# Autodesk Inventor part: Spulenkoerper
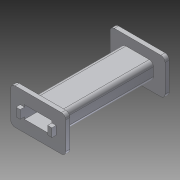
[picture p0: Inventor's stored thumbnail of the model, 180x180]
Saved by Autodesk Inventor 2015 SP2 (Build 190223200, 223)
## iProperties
Created: 2015-10
Part Number: Spulenkoerper
Material: PC/ABS-Kunststoff
Document SubType Name: Modeling
Designer: rYan
Mass: 0.345661 g
Surface Area: 21.13 cm^2
Volume: 0.9675 cm^3
Density: 0.357273 g/cm^3
Appearance: Glatt - weiß
Author: rYan
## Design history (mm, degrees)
sketch "Skizze1"
  geometry: L1 (-10.5, 0)-(10.5, 0) reference; L2 (0, -0.8)-(0, 4.8) reference; L3 (6.5, 3)-(-6.5, 3); L4 (-6.5, 3)-(-6.5, 0); L5 (6.5, 3)-(6.5, 0); L6 (-6.5, 0)-(-7.5, 0); L7 (-7.5, 0)-(-7.5, 4); L8 (-7.5, 4)-(7.5, 4); L9 (7.5, 4)-(7.5, 0); L10 (7.5, 0)-(6.5, 0); 1 further point
  constraints: 17 end point, 4 perpendicular, 3 point on line, 2 horizontal, 1 parallel, 2 other
  dimensions: "d0" = 13 distance of L3.start L3.end; "d1" = 3 distance between parallel lines of L1 L3; "d2" = 1 distance between parallel lines of L8 L3; "d3" = 1 distance between parallel lines of L4 L7
extrude "Extrusion1" new body sketch "Skizze1" stored distance "d6" = 45; taper "d7" = 0 deg
sketch "Skizze2"
  geometry: L1 (-13, 8.5)-(13, 8.5); L2 (13, 8.5)-(13, 0); L3 (13, 0)-(6.5, 0); L4 (6.5, 0)-(6.5, 3); L5 (6.5, 3)-(-6.5, 3); L6 (-6.5, 3)-(-6.5, 0); L7 (-6.5, 0)-(-13, 0); L8 (-13, 0)-(-13, 8.5); L9 (0, 10.2)-(0, -1.7) reference; L10 (-18.2, 0)-(18.2, 0) reference; L11 (-6.5, 0)-(-6.5, 3) reference; L12 (-6.5, 3)-(6.5, 3) reference; 1 further point
  constraints: 16 end point, 6 perpendicular, 3 collinear, 2 point on line, 1 horizontal, 2 other
  dimensions: "d10" = 26 distance of L1.start L1.end; "d11" = 8.5 distance between parallel lines of L10 L1
extrude "Extrusion2" join sketch "Skizze2" distance "d13" = 2; taper "d14" = 0 deg
sketch "Skizze3"
  geometry: L1 (8.5, 2)-(8.5, 0); L2 (8.5, 0)-(6.5, 0); L3 (6.5, 0)-(6.5, 2); L4 (0, 10.2)-(0, -1.7) reference; L5 (-6.5, 0)-(-6.5, 3) reference; L6 (-6.5, 3)-(6.5, 3) reference; L7 (-18.2, 0)-(18.2, 0) reference; L8 (6.5, 2)-(8.5, 2); L9 (6.5, 3)-(6.5, 0) reference; L10 (-6.5, 0)-(-8.5, 0); L11 (-8.5, 0)-(-8.5, 2); L12 (-8.5, 2)-(-6.5, 2); L13 (-6.5, 2)-(-6.5, 0); 1 further point
  constraints: 16 end point, 3 perpendicular, 2 horizontal, 2 parallel, 1 collinear, 2 other
  dimensions: "d36" = 2 distance of L11.end L12.end; "d37" = 2 distance of L10.end L11.end
extrude "Extrusion3" join sketch "Skizze3" distance "d17" = 2; taper "d18" = 0 deg
mirror "Spiegeln1"
sketch "Skizze4"
  geometry: L1 (6.5, -26.5)-(6.5, 26.5) reference; L2 (7.5, -22.5)-(7.5, 22.5) reference; L3 (13, -22.5)-(7.5, -22.5) reference; L4 (13, -22.5)-(13, -24.5) reference; L5 (8.5, -24.5)-(13, -24.5) reference; L6 (-7.5, 22.5)-(-7.5, -22.5) reference; L7 (-6.5, -26.5)-(-6.5, 26.5) reference; L8 (-13, -24.5)-(-8.5, -24.5) reference; L9 (-13, -22.5)-(-13, -24.5) reference; L10 (-7.5, -22.5)-(-13, -22.5) reference; L11 (8.5, -24.5)-(8.5, -26.5) reference; L12 (6.5, -26.5)-(8.5, -26.5) reference; L13 (-9, -24.5)-(-13, -24.5); L14 (-13, -24.5)-(-13, -23.5); L15 (-13, -23.5)-(-9, -23.5); L16 (-9, -23.5)-(-9, -24.5); L17 (9, 24.5)-(13, 24.5); L18 (13, 24.5)-(13, 23.5); L19 (13, 23.5)-(9, 23.5); L20 (9, 23.5)-(9, 24.5); L21 (-7.5, 22.5)-(-13, 22.5) reference; L22 (-13, 22.5)-(-13, 24.5) reference; L23 (-13, 24.5)-(-8.5, 24.5) reference; L24 (6.5, 26.5)-(8.5, 26.5) reference; L25 (8.5, 24.5)-(8.5, 26.5) reference; L26 (8.5, 24.5)-(13, 24.5) reference; L27 (13, 22.5)-(13, 24.5) reference; L28 (13, 22.5)-(7.5, 22.5) reference; L29 (8.5, 24.5)-(13, 24.5) reference; L30 (-8.5, 24.5)-(-8.5, 26.5) reference; L31 (-8.5, 26.5)-(-6.5, 26.5) reference; L32 (-8.5, -26.5)-(-6.5, -26.5) reference; L33 (-8.5, -24.5)-(-8.5, -26.5) reference; 2 further points
  constraints: 16 end point, 4 parallel, 2 collinear, 2 horizontal, 2 midpoint, 2 perpendicular, 2 point on line
  dimensions: "d23" = 4 distance of L14.end L15.end; "d24" = 4 distance of L18.end L19.end
extrude "Extrusion4" join sketch "Skizze4" distance "d19" = 1; taper "d20" = 0 deg
sketch "Skizze6"
  geometry: L1 (6.5, -26.5)-(6.5, 26.5) reference; L2 (7.5, -22.5)-(7.5, 22.5) reference; L3 (13, -22.5)-(7.5, -22.5) reference; L4 (13, -22.5)-(13, -24.5) reference; L5 (8.5, -24.5)-(13, -24.5) reference; L6 (-7.5, 22.5)-(-7.5, -22.5) reference; L7 (-6.5, -26.5)-(-6.5, 26.5) reference; L8 (-13, -22.5)-(-13, -24.5) reference; L9 (-7.5, -22.5)-(-13, -22.5) reference; L10 (8.5, -24.5)-(8.5, -26.5) reference; L11 (6.5, -26.5)-(8.5, -26.5) reference; L12 (-13, -24.5)-(-8.5, -24.5) reference; L13 (9, -24.5)-(13, -24.5); L14 (13, -24.5)-(13, -23.5); L15 (13, -23.5)-(9, -23.5); L16 (9, -23.5)-(9, -24.5); L17 (-9, 24.5)-(-13, 24.5); L18 (-13, 24.5)-(-13, 23.5); L19 (-13, 23.5)-(-9, 23.5); L20 (-9, 23.5)-(-9, 24.5); L21 (-7.5, 22.5)-(-13, 22.5) reference; L22 (-13, 22.5)-(-13, 24.5) reference; L23 (-13, 24.5)-(-8.5, 24.5) reference; L24 (13, 22.5)-(13, 24.5) reference; L25 (13, 22.5)-(7.5, 22.5) reference; L26 (6.5, 26.5)-(8.5, 26.5) reference; L27 (8.5, 24.5)-(8.5, 26.5) reference; L28 (8.5, 24.5)-(13, 24.5) reference; L29 (-8.5, 24.5)-(-8.5, 26.5) reference; L30 (-8.5, 26.5)-(-6.5, 26.5) reference; L31 (-8.5, -26.5)-(-6.5, -26.5) reference; L32 (-8.5, -24.5)-(-8.5, -26.5) reference; 1 further point
  constraints: 16 end point, 4 parallel, 2 horizontal, 2 perpendicular, 1 midpoint, 1 point on line
  dimensions: "d25" = 4 distance of L14.end L15.end; "d26" = 4 distance of L18.end L19.end
extrude "Extrusion5" cut sketch "Skizze6" distance "d21" = 1; taper "d22" = 0 deg
fillet "Rundung2" dims "d31" = 2
fillet "Rundung3" dims "d32" = 1
fillet "Rundung5" dims "d39" = 1
mirror "Mirror2"
node "Volumenkörper1"
node "Projizierte Kontur1"
node "Projizierte Kontur2"
node "Projizierte Kontur3"
node "Projizierte Kontur4"
